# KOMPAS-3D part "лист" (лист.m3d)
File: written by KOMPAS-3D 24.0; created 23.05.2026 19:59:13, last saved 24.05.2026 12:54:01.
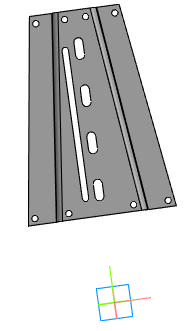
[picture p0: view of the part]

Document properties: Автор: R2D2; Полное имя файла: E:\Работа\Зайцев\GVKR1331M-1W-Fb-2P Задвижка шиберная с выдвижным штоком DN.ru Ду50-300 Ру16-10-6 с пневмоприводом\исходные материалы\DN150\лист.m3d

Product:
- Part/product: лист
    Масса: 2.142327
    Раздел спецификации: Прочие изделия
    Примечание: D040-08800

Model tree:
1. Эскиз:6  (with: Грань.Элемент выдавливания:15, Ребро.Элемент выдавливания:15)
2. Эскиз:7  (with: Грань.Элемент выдавливания:6, Ребро.Элемент выдавливания:6, Ребро.Элемент выдавливания:12)
3. Линейчатая обечайка:1
     Расстояние 1 = 10; Толщина листового тела = 4; Коэффициент = 0.5
4. Сгиб(1) - Линейчатая обечайка:1
     Радиус сгиба = 5; Коэффициент = 0.5; Величина сгиба = 5
5. Сгиб(2) - Линейчатая обечайка:1
     Радиус сгиба = 5; Коэффициент = 0.5; Величина сгиба = 5
6. Сгиб(3) - Линейчатая обечайка:1
     Радиус сгиба = 5; Коэффициент = 0.5; Величина сгиба = 5
7. Сгиб(4) - Линейчатая обечайка:1
     Радиус сгиба = 5; Коэффициент = 0.5; Величина сгиба = 5; Зазор = 1; Угол = 360; Параметр U, % = 100; Длина = 149
8. Эскиз:8  (with: Грань.Линейчатая обечайка:1, Ребро.Линейчатая обечайка:1)
9. Отверстие в листовом теле:1  (with: Грань.Линейчатая обечайка:1, Ребро.Линейчатая обечайка:1)
     Глубина выреза = 10; Расстояние 1 = 10; Расстояние 2 = 10
10. Отверстие в листовом теле:2  (with: Грань.Линейчатая обечайка:1, Ребро.Линейчатая обечайка:1)
     Глубина выреза = 10; Расстояние 1 = -10; Расстояние 2 = 10
11. Отверстие в листовом теле:3  (with: Грань.Линейчатая обечайка:1, Ребро.Линейчатая обечайка:1)
     Глубина выреза = 10; Расстояние 1 = -110.601; Расстояние 2 = 10
12. Отверстие в листовом теле:4  (with: Грань.Линейчатая обечайка:1, Ребро.Линейчатая обечайка:1)
     Глубина выреза = 10; Расстояние 1 = -33.0028; Расстояние 2 = 10
13. Отверстие в листовом теле:5  (with: Грань.Линейчатая обечайка:1, Ребро.Линейчатая обечайка:1)
     Глубина выреза = 10; Расстояние 1 = 10; Расстояние 2 = 308.5
14. Отверстие в листовом теле:6  (with: Грань.Линейчатая обечайка:1, Ребро.Линейчатая обечайка:1)
     Глубина выреза = 10; Расстояние 1 = -10; Расстояние 2 = 308.5
15. Отверстие в листовом теле:7  (with: Грань.Линейчатая обечайка:1, Ребро.Линейчатая обечайка:1)
     Глубина выреза = 10; Расстояние 1 = -42.4613; Расстояние 2 = 308.5
16. Отверстие в листовом теле:8  (with: Грань.Линейчатая обечайка:1, Ребро.Линейчатая обечайка:1)
     Глубина выреза = 10; Расстояние 1 = -25.0382; Расстояние 2 = 308.5
17. Эскиз:9  (with: Грань.Линейчатая обечайка:1, Ребро.Линейчатая обечайка:1)
18. Эскиз:10  (with: Грань.Линейчатая обечайка:1, Ребро.Линейчатая обечайка:1)
19. Вырез в листовом теле:1
     Глубина выреза = 10
20. Вырез в листовом теле:2
     Глубина выреза = 10
21. Массив по сетке:1  (with: Вырез в листовом теле:2, Эскиз:9, Эскиз:10)  (4 pattern instances)
     Угол раствора = 90; Геометрический массив = 128

Expressions: 2*h; v1424-100
Referenced files in E:\Работа\Зайцев\GVKR1331M-1W-Fb-2P Задвижка шиберная с выдвижным штоком DN.ru Ду50-300 Ру16-10-6 с пневмоприводом\исходные материалы\DN150\: GVKR1331M-1W-Fb-2P Задвижка шиберная с выдвижным штоком DN.ru Ду150 Ру10.a3d
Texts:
  Затвор дисковый DN.ru Ду Ру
